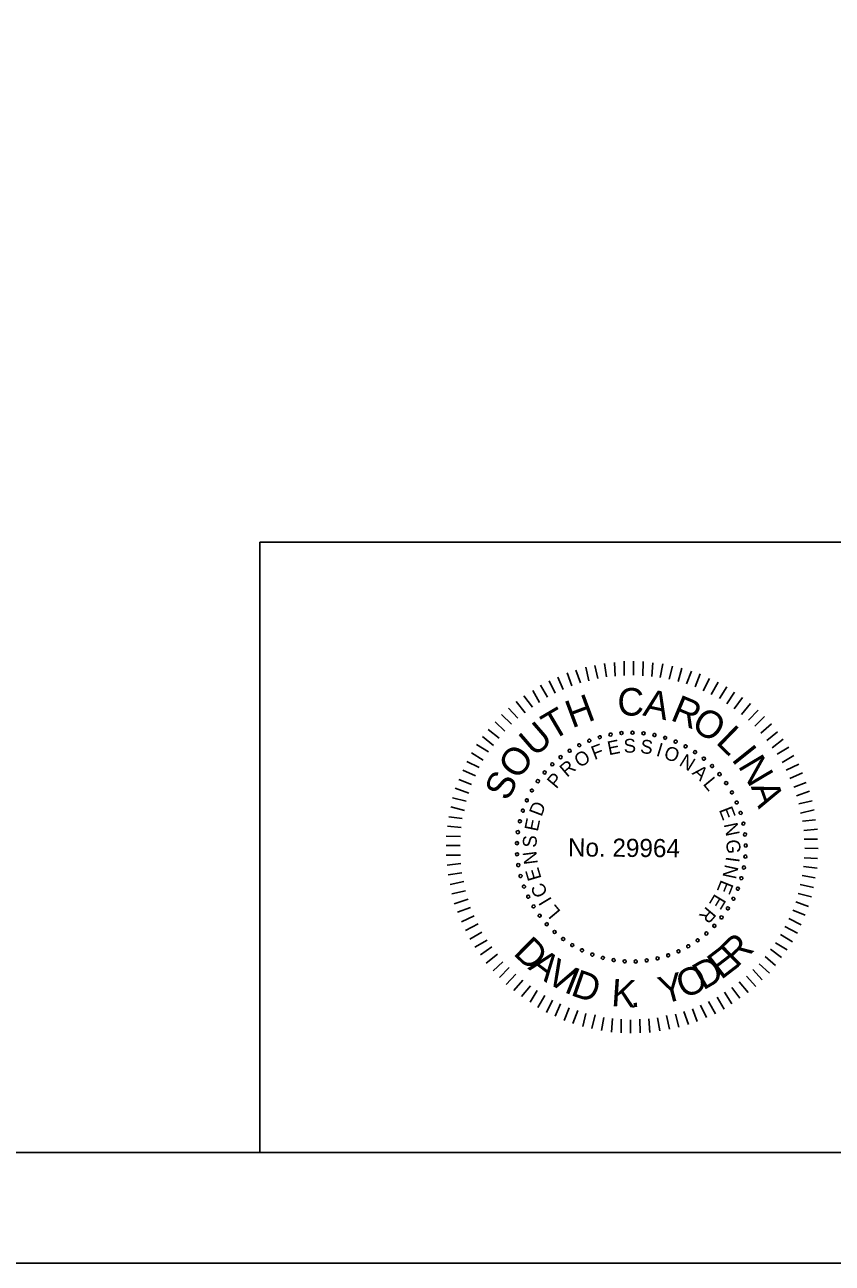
# Model space of a CAD drawing. Extents: x -121.2 to -24.9, y 6.4 to 65.9.
# Drawn here: x -63.63 to -53.93, y 6.35 to 21.24 of the extents above; entities that cross this region are included whole.
import ezdxf

# ---------------------------------------------------------------- set-up
doc = ezdxf.new("R2010")
doc.units = 0
for name, color, linetype in [('BR_BORDER LINES', 7, 'Continuous'), ('BR_TEXT', 7, 'Continuous'), ('Level 31', 7, 'Continuous')]:
    doc.layers.add(name, color=color, linetype=linetype)

msp = doc.modelspace()

# ---------------------------------------------------------------- linework, layer by layer
at = {"layer": 'BR_BORDER LINES'}
for p, q in [((-60.804, 15.017), (-46.496, 15.017)), ((-60.804, 7.683), (-60.804, 15.017)), ((-116.272, 7.683), (-26.496, 7.683))]:
    msp.add_line(p, q, dxfattribs=at)
at = {"layer": 'BR_TEXT'}
for p, q in [((-56.639, 13.398), (-56.663, 13.561)), ((-56.534, 13.409), (-56.544, 13.572)), ((-56.428, 13.415), (-56.427, 13.587)), ((-56.316, 13.421), (-56.315, 13.586)), ((-56.204, 13.413), (-56.198, 13.585)), ((-56.097, 13.405), (-56.084, 13.568)), ((-55.994, 13.393), (-55.965, 13.555)), ((-57.056, 13.292), (-57.112, 13.448)), ((-56.951, 13.326), (-57.009, 13.479)), ((-56.854, 13.352), (-56.89, 13.515)), ((-56.744, 13.379), (-56.782, 13.537)), ((-55.886, 13.372), (-55.848, 13.529)), ((-55.777, 13.343), (-55.734, 13.505)), ((-55.679, 13.315), (-55.62, 13.468)), ((-55.574, 13.28), (-55.515, 13.435)), ((-57.35, 13.155), (-57.432, 13.3)), ((-57.258, 13.202), (-57.328, 13.351)), ((-57.16, 13.247), (-57.223, 13.396)), ((-55.478, 13.233), (-55.403, 13.381)), ((-55.382, 13.187), (-55.298, 13.335)), ((-55.282, 13.138), (-55.196, 13.281)), ((-57.528, 13.035), (-57.632, 13.171)), ((-57.445, 13.092), (-57.526, 13.236)), ((-55.193, 13.073), (-55.103, 13.216)), ((-55.104, 13.015), (-55.007, 13.149)), ((-57.705, 12.902), (-57.816, 13.021)), ((-57.617, 12.967), (-57.724, 13.101)), ((-55.018, 12.946), (-54.909, 13.078)), ((-54.934, 12.879), (-54.818, 12.997)), ((-57.862, 12.747), (-57.978, 12.86)), ((-57.783, 12.829), (-57.901, 12.947)), ((-54.859, 12.805), (-54.743, 12.921)), ((-54.784, 12.722), (-54.657, 12.833)), ((-57.998, 12.574), (-58.13, 12.681)), ((-57.929, 12.663), (-58.061, 12.767)), ((-54.712, 12.636), (-54.587, 12.738)), ((-58.056, 12.497), (-58.2, 12.585)), ((-54.648, 12.547), (-54.517, 12.651)), ((-54.589, 12.468), (-54.449, 12.554)), ((-58.168, 12.308), (-58.318, 12.382)), ((-58.121, 12.399), (-58.264, 12.485)), ((-54.531, 12.37), (-54.388, 12.453)), ((-58.214, 12.21), (-58.367, 12.278)), ((-54.483, 12.278), (-54.329, 12.35)), ((-54.436, 12.179), (-54.284, 12.244)), ((-58.294, 12), (-58.458, 12.061)), ((-58.261, 12.107), (-58.416, 12.166)), ((-54.391, 12.075), (-54.24, 12.131)), ((-58.326, 11.904), (-58.489, 11.945)), ((-54.355, 11.968), (-54.202, 12.026)), ((-58.346, 11.792), (-58.512, 11.835)), ((-54.329, 11.871), (-54.168, 11.909)), ((-54.307, 11.759), (-54.146, 11.799)), ((-58.374, 11.696), (-58.536, 11.718)), ((-54.285, 11.663), (-54.127, 11.682)), ((-58.394, 11.481), (-58.566, 11.483)), ((-58.386, 11.587), (-58.551, 11.606)), ((-54.267, 11.553), (-54.105, 11.57)), ((-58.4, 11.372), (-58.567, 11.373)), ((-54.264, 11.447), (-54.103, 11.446)), ((-54.258, 11.338), (-54.095, 11.336)), ((-58.396, 11.257), (-58.568, 11.254)), ((-54.265, 11.223), (-54.105, 11.217)), ((-58.39, 11.154), (-58.555, 11.135)), ((-58.379, 11.044), (-58.542, 11.02)), ((-54.271, 11.12), (-54.109, 11.098)), ((-58.353, 10.939), (-58.52, 10.904)), ((-54.314, 10.905), (-54.154, 10.867)), ((-54.29, 11.011), (-54.132, 10.984)), ((-58.335, 10.826), (-58.498, 10.789)), ((-58.304, 10.728), (-58.469, 10.672)), ((-54.338, 10.793), (-54.178, 10.753)), ((-58.273, 10.625), (-58.429, 10.569)), ((-54.403, 10.593), (-54.253, 10.534)), ((-54.366, 10.695), (-54.213, 10.637)), ((-58.228, 10.526), (-58.382, 10.454)), ((-58.183, 10.429), (-58.335, 10.35)), ((-54.45, 10.495), (-54.3, 10.42)), ((-58.138, 10.331), (-58.283, 10.247)), ((-54.548, 10.301), (-54.407, 10.215)), ((-54.499, 10.399), (-54.346, 10.318)), ((-58.075, 10.232), (-58.22, 10.148)), ((-58.018, 10.153), (-58.152, 10.056)), ((-54.668, 10.126), (-54.539, 10.026)), ((-54.608, 10.203), (-54.469, 10.117)), ((-57.95, 10.064), (-58.084, 9.959)), ((-54.733, 10.037), (-54.61, 9.931)), ((-57.885, 9.974), (-58.002, 9.865)), ((-57.808, 9.904), (-57.927, 9.784)), ((-54.883, 9.88), (-54.77, 9.758)), ((-54.807, 9.948), (-54.682, 9.837)), ((-57.73, 9.824), (-57.844, 9.701)), ((-57.644, 9.754), (-57.753, 9.629)), ((-57.555, 9.685), (-57.662, 9.558)), ((-55.044, 9.733), (-54.938, 9.606)), ((-54.959, 9.801), (-54.846, 9.676)), ((-57.473, 9.627), (-57.557, 9.488)), ((-57.38, 9.567), (-57.464, 9.423)), ((-55.311, 9.55), (-55.228, 9.405)), ((-55.222, 9.608), (-55.134, 9.468)), ((-55.132, 9.665), (-55.037, 9.536)), ((-57.289, 9.513), (-57.361, 9.365)), ((-57.191, 9.467), (-57.256, 9.319)), ((-57.088, 9.42), (-57.147, 9.27)), ((-56.983, 9.387), (-57.044, 9.232)), ((-55.606, 9.408), (-55.55, 9.256)), ((-55.509, 9.453), (-55.437, 9.304)), ((-55.413, 9.498), (-55.331, 9.348)), ((-56.888, 9.354), (-56.925, 9.197)), ((-56.778, 9.335), (-56.818, 9.171)), ((-56.673, 9.305), (-56.699, 9.149)), ((-56.568, 9.292), (-56.58, 9.128)), ((-56.462, 9.285), (-56.464, 9.12)), ((-56.35, 9.277), (-56.352, 9.114)), ((-56.238, 9.283), (-56.235, 9.118)), ((-56.131, 9.289), (-56.121, 9.124)), ((-56.028, 9.299), (-56.001, 9.143)), ((-55.92, 9.328), (-55.884, 9.163)), ((-55.81, 9.346), (-55.77, 9.187)), ((-55.711, 9.377), (-55.655, 9.221))]:
    msp.add_line(p, q, dxfattribs=at)
for centre, start, end in [((-56.721, 12.674), 16.1422, 196.1422), ((-56.721, 12.674), 196.1422, 16.1422), ((-56.592, 12.705), 10.6038, 190.6038), ((-56.592, 12.705), 190.6038, 10.6038), ((-56.46, 12.723), 5.0653, 185.0653), ((-56.46, 12.723), 185.0653, 5.0653), ((-56.328, 12.728), 359.5268, 179.5268), ((-56.328, 12.728), 179.5268, 359.5268), ((-56.195, 12.72), 353.9884, 173.9884), ((-56.195, 12.72), 173.9884, 353.9884), ((-56.064, 12.699), 348.4499, 168.4499), ((-56.064, 12.699), 168.4499, 348.4499), ((-55.935, 12.666), 162.9114, 342.9114), ((-55.935, 12.666), 342.9114, 162.9114), ((-57.083, 12.511), 32.7576, 212.7576), ((-57.083, 12.511), 212.7576, 32.7576), ((-56.968, 12.577), 27.2191, 207.2191), ((-56.968, 12.577), 207.2191, 27.2191), ((-56.847, 12.632), 21.6807, 201.6807), ((-56.847, 12.632), 201.6807, 21.6807), ((-55.81, 12.621), 157.373, 337.373), ((-55.81, 12.621), 337.373, 157.373), ((-55.69, 12.564), 151.8345, 331.8345), ((-55.69, 12.564), 331.8345, 151.8345), ((-55.576, 12.495), 326.2961, 146.2961), ((-57.292, 12.347), 43.8345, 223.8345), ((-57.292, 12.347), 223.8345, 43.8345), ((-57.192, 12.434), 38.2961, 218.2961), ((-57.192, 12.434), 218.2961, 38.2961), ((-55.576, 12.495), 146.2961, 326.2961), ((-55.47, 12.416), 140.7576, 320.7576), ((-55.47, 12.416), 320.7576, 140.7576), ((-57.384, 12.25), 49.373, 229.373), ((-57.384, 12.25), 229.373, 49.373), ((-55.371, 12.327), 135.2191, 315.2191), ((-55.371, 12.327), 315.2191, 135.2191), ((-55.282, 12.229), 129.6807, 309.6807), ((-55.282, 12.229), 309.6807, 129.6807), ((-57.465, 12.145), 54.9114, 234.9114), ((-57.465, 12.145), 234.9114, 54.9114), ((-55.202, 12.122), 124.1422, 304.1422), ((-55.202, 12.122), 304.1422, 124.1422), ((-57.597, 11.915), 65.9884, 245.9884), ((-57.597, 11.915), 245.9884, 65.9884), ((-57.537, 12.033), 60.4499, 240.4499), ((-57.537, 12.033), 240.4499, 60.4499), ((-55.133, 12.009), 118.6038, 298.6038), ((-55.133, 12.009), 298.6038, 118.6038), ((-57.645, 11.791), 71.5268, 251.5268), ((-57.645, 11.791), 251.5268, 71.5268), ((-55.075, 11.889), 113.0653, 293.0653), ((-55.075, 11.889), 293.0653, 113.0653), ((-55.029, 11.764), 107.5268, 287.5268), ((-55.029, 11.764), 287.5268, 107.5268), ((-57.681, 11.663), 77.0653, 257.0653), ((-57.681, 11.663), 257.0653, 77.0653), ((-54.996, 11.636), 101.9884, 281.9884), ((-54.996, 11.636), 281.9884, 101.9884), ((-57.705, 11.532), 82.6038, 262.6038), ((-57.705, 11.532), 262.6038, 82.6038), ((-54.975, 11.504), 96.4499, 276.4499), ((-54.975, 11.504), 276.4499, 96.4499), ((-57.716, 11.4), 88.1422, 268.1422), ((-57.716, 11.4), 268.1422, 88.1422), ((-54.967, 11.372), 90.9114, 270.9114), ((-54.967, 11.372), 270.9114, 90.9114), ((-57.714, 11.267), 93.6807, 273.6807), ((-57.714, 11.267), 273.6807, 93.6807), ((-54.971, 11.239), 85.373, 265.373), ((-54.971, 11.239), 265.373, 85.373), ((-57.7, 11.135), 99.2191, 279.2191), ((-57.7, 11.135), 279.2191, 99.2191), ((-57.672, 11.005), 104.7576, 284.7576), ((-57.672, 11.005), 284.7576, 104.7576), ((-54.989, 11.107), 79.8345, 259.8345), ((-54.989, 11.107), 259.8345, 79.8345), ((-57.632, 10.878), 110.2961, 290.2961), ((-57.632, 10.878), 290.2961, 110.2961), ((-55.061, 10.852), 68.7576, 248.7576), ((-55.061, 10.852), 248.7576, 68.7576), ((-55.019, 10.978), 74.2961, 254.2961), ((-55.019, 10.978), 254.2961, 74.2961), ((-57.581, 10.756), 115.8345, 295.8345), ((-57.581, 10.756), 295.8345, 115.8345), ((-55.115, 10.731), 63.2191, 243.2191), ((-55.115, 10.731), 243.2191, 63.2191), ((-57.517, 10.639), 121.373, 301.373), ((-57.517, 10.639), 301.373, 121.373), ((-55.181, 10.615), 57.6807, 237.6807), ((-55.181, 10.615), 237.6807, 57.6807), ((-57.443, 10.529), 126.9114, 306.9114), ((-57.443, 10.529), 306.9114, 126.9114), ((-57.358, 10.426), 132.4499, 312.4499), ((-57.358, 10.426), 312.4499, 132.4499), ((-55.344, 10.406), 46.6038, 226.6038), ((-55.258, 10.507), 52.1422, 232.1422), ((-55.258, 10.507), 232.1422, 52.1422), ((-57.264, 10.333), 137.9884, 317.9884), ((-57.264, 10.333), 317.9884, 137.9884), ((-55.44, 10.314), 41.0653, 221.0653), ((-55.44, 10.314), 221.0653, 41.0653), ((-55.344, 10.406), 226.6038, 46.6038), ((-57.161, 10.248), 143.5268, 323.5268), ((-57.161, 10.248), 323.5268, 143.5268), ((-57.051, 10.174), 149.0653, 329.0653), ((-57.051, 10.174), 329.0653, 149.0653), ((-56.934, 10.112), 334.6038, 154.6038), ((-55.657, 10.16), 29.9884, 209.9884), ((-55.657, 10.16), 209.9884, 29.9884), ((-55.545, 10.232), 35.5268, 215.5268), ((-55.545, 10.232), 215.5268, 35.5268), ((-56.934, 10.112), 154.6038, 334.6038), ((-56.811, 10.06), 160.1422, 340.1422), ((-56.811, 10.06), 340.1422, 160.1422), ((-56.684, 10.021), 345.6807, 165.6807), ((-56.684, 10.021), 165.6807, 345.6807), ((-56.554, 9.994), 351.2191, 171.2191), ((-56.554, 9.994), 171.2191, 351.2191), ((-56.422, 9.98), 356.7576, 176.7576), ((-56.422, 9.98), 176.7576, 356.7576), ((-56.289, 9.978), 2.2961, 182.2961), ((-56.289, 9.978), 182.2961, 2.2961), ((-56.157, 9.99), 7.8345, 187.8345), ((-56.157, 9.99), 187.8345, 7.8345), ((-56.026, 10.014), 13.373, 193.373), ((-56.026, 10.014), 193.373, 13.373), ((-55.899, 10.051), 18.9114, 198.9114), ((-55.899, 10.051), 198.9114, 18.9114), ((-55.775, 10.1), 24.4499, 204.4499), ((-55.775, 10.1), 204.4499, 24.4499)]:
    msp.add_arc(centre, 0.0187, start, end, dxfattribs=at)
at = {"layer": 'Level 31'}
msp.add_lwpolyline([(-121.161, 6.35), (-25.161, 6.35), (-25.161, 65.017), (-121.161, 65.017)], close=True, dxfattribs=at)

# ---------------------------------------------------------------- texts
at = {"layer": 'BR_TEXT'}
for s, height, rotation, p in [('C', 0.331, 359.5482, (-56.51, 12.935)), ('H', 0.331, 20.3637, (-57.055, 12.779)), ('A', 0.331, 348.1981, (-56.213, 12.937)), ('R', 0.331, 337.4344, (-55.884, 12.884)), ('T', 0.331, 30.4992, (-57.29, 12.626)), ('O', 0.33, 326.5869, (-55.638, 12.786)), ('U', 0.331, 40.8022, (-57.506, 12.426)), ('L', 0.331, 315.9488, (-55.338, 12.605)), ('S', 0.166, 2.208, (-56.431, 12.485)), ('O', 0.331, 52.0267, (-57.705, 12.149)), ('F', 0.166, 20.6127, (-56.785, 12.398)), ('E', 0.166, 11.4103, (-56.611, 12.456)), ('S', 0.166, 352.6608, (-56.241, 12.485)), ('I', 0.166, 343.1136, (-56.053, 12.453)), ('O', 0.166, 338.4392, (-55.964, 12.426)), ('I', 0.331, 308.6613, (-55.148, 12.407)), ('R', 0.166, 40.3949, (-57.115, 12.185)), ('O', 0.166, 30.8477, (-56.965, 12.302)), ('N', 0.166, 328.2042, (-55.778, 12.342)), ('N', 0.331, 300.7037, (-55.066, 12.329)), ('S', 0.33, 63.2511, (-57.826, 11.894)), ('P', 0.166, 49.9421, (-57.243, 12.045)), ('A', 0.166, 318.657, (-55.621, 12.235)), ('L', 0.166, 309.4546, (-55.488, 12.109)), ('A', 0.331, 289.4792, (-54.908, 12.081)), ('D', 0.166, 69.0364, (-57.421, 11.711)), ('E', 0.166, 291.049, (-55.291, 11.801)), ('E', 0.166, 78.2388, (-57.466, 11.533)), ('N', 0.166, 281.8466, (-55.232, 11.628)), ('S', 0.166, 87.786, (-57.481, 11.344)), ('No. 29964', 0.218, 359.5268, (-57.104, 11.241)), ('G', 0.166, 272.2995, (-55.201, 11.441)), ('N', 0.166, 97.3332, (-57.464, 11.154)), ('I', 0.166, 262.4084, (-55.202, 11.244)), ('E', 0.166, 106.5355, (-57.419, 10.977)), ('N', 0.166, 257.7339, (-55.214, 11.151)), ('C', 0.166, 116.4266, (-57.339, 10.797)), ('E', 0.166, 248.1867, (-55.262, 10.968)), ('I', 0.166, 121.1011, (-57.291, 10.717)), ('E', 0.166, 238.9844, (-55.337, 10.8)), ('L', 0.166, 129.9595, (-57.183, 10.578)), ('R', 0.166, 229.782, (-55.437, 10.647)), ('D', 0.329, 315.4053, (-57.771, 10.07)), ('R', 0.329, 44.5947, (-55.075, 9.895)), ('E', 0.329, 37.5339, (-55.263, 9.751)), ('A', 0.329, 322.8377, (-57.593, 9.895)), ('V', 0.329, 330.5179, (-57.387, 9.739)), ('D', 0.329, 30.1015, (-55.479, 9.626)), ('I', 0.329, 338.1981, (-57.163, 9.613)), ('D', 0.329, 340.7995, (-57.083, 9.577)), ('Y', 0.329, 14.8649, (-55.962, 9.462)), ('O', 0.329, 22.4212, (-55.717, 9.527)), ('K', 0.329, 356.098, (-56.589, 9.442)), ('.', 0.329, 3.1588, (-56.353, 9.426))]:
    msp.add_text(s, height=height, rotation=rotation, dxfattribs=at).set_placement(p)

doc.saveas('drawing.dxf')
